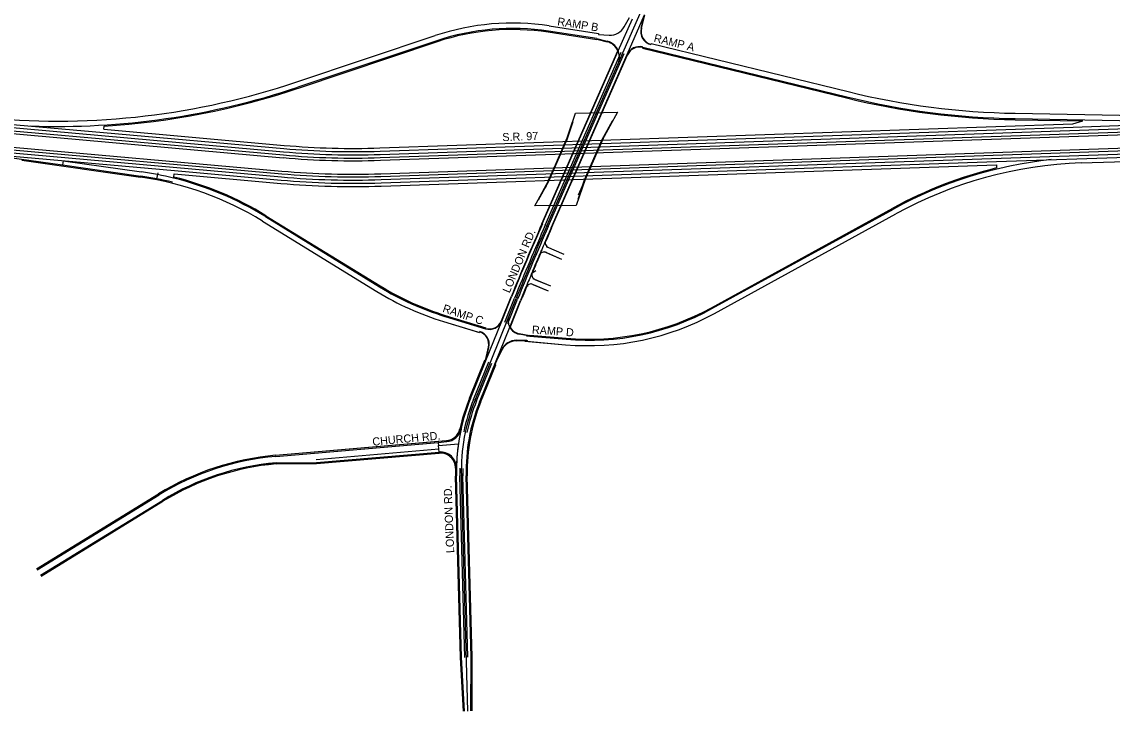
# Model space of a CAD drawing. Extents: x 2315515 to 2326910, y 758186 to 762794.
# Drawn here: x 2318941 to 2323003, y 758186 to 760752 of the extents above; entities that cross this region are included whole.
import ezdxf

# ---------------------------------------------------------------- set-up
doc = ezdxf.new("R2010")
doc.units = 0
for name, color, linetype in [('_CIVIL_CONSTRUCTION', 7, 'Continuous'), ('Bridge_Abutment', 7, 'Continuous'), ('Bridge_Bearing', 7, 'Continuous'), ('Bridge_Deck', 7, 'Continuous'), ('Clipping_Shape', 7, 'Continuous'), ('Default', 7, 'Continuous'), ('Draft_Corr_Final', 7, 'Continuous'), ('Draft_Corr_Range_Final', 7, 'Continuous'), ('Pavement Marking Yellow', 7, 'Continuous'), ('Road_Curb_Face', 7, 'Continuous'), ('TL_Base Extension Sub', 7, 'Continuous'), ('TL_End Condition Cut Tie', 7, 'Continuous'), ('TL_End Condition Ditch Out', 7, 'Continuous'), ('TL_End Condition Hinge', 7, 'Continuous'), ('TL_Pavement Centerline', 7, 'Continuous'), ('TL_Pavement Centerline Sub', 7, 'Continuous')]:
    doc.layers.add(name, color=color, linetype=linetype)

msp = doc.modelspace()

# ---------------------------------------------------------------- linework, layer by layer
at = {"layer": '_CIVIL_CONSTRUCTION'}
for p, q in [((2315523.8, 760636.9), (2319914.5, 760246.1)), ((2315519.4, 760587.1), (2319910, 760196.3)), ((2320276.8, 760236.3), (2324006.3, 760365.3)), ((2320278.5, 760186.3), (2324008.1, 760315.3))]:
    msp.add_line(p, q, dxfattribs=at)
for radius in [2941, 2991]:
    msp.add_arc((2320175.2, 763175.6), radius, 264.9144, 271.9805, dxfattribs=at)
at = {"layer": 'Bridge_Abutment'}
for p, q in [((2320970, 760308.5), (2320994, 760379.5)), ((2321103.2, 760313.3), (2321141.6, 760383.5)), ((2320904.4, 760159.2), (2320970, 760308.5)), ((2321037.2, 760163.2), (2321103.2, 760313.3)), ((2320866, 760089.1), (2320904.4, 760159.2)), ((2321013.2, 760092.1), (2321037.2, 760163.2))]:
    msp.add_line(p, q, dxfattribs=at)
at = {"layer": 'Bridge_Bearing'}
for p, q in [((2320994, 760379.5), (2320970, 760308.5)), ((2321141.6, 760383.5), (2321103.2, 760313.3)), ((2320904.4, 760159.2), (2320970, 760308.5)), ((2321037.2, 760163.2), (2321103.2, 760313.3)), ((2320866, 760089.1), (2320904.4, 760159.2)), ((2321013.2, 760092.1), (2321037.2, 760163.2))]:
    msp.add_line(p, q, dxfattribs=at)
at = {"layer": 'Bridge_Deck'}
for p, q in [((2320891.3, 760134.3), (2320977.7, 760331.1)), ((2320946.3, 760259.5), (2320966.8, 760306.2)), ((2321014.9, 760107.4), (2321107.7, 760318.6)), ((2321083.8, 760264.2), (2321104.3, 760311)), ((2320903.4, 760161.9), (2320924, 760208.7)), ((2321041, 760166.7), (2321061.5, 760213.4))]:
    msp.add_line(p, q, dxfattribs=at)
at = {"layer": 'Clipping_Shape'}
for p, q in [((2320969.1, 760308.8), (2320993.1, 760379.8)), ((2320903.6, 760159.7), (2320969.1, 760308.8)), ((2320865.1, 760089.5), (2320903.6, 760159.7))]:
    msp.add_line(p, q, dxfattribs=at)
msp.add_lwpolyline([(2320852.2, 760066.2), (2320904.3, 760161.4), (2320968.5, 760307.7), (2321003.8, 760411.9), (2321160.3, 760415.2), (2321103.4, 760311.5), (2321039.2, 760165.2), (2321006.2, 760067.6)], close=True, dxfattribs=at)
at = {"layer": 'Default'}
for p, q in [((2320896.6, 759992.2), (2321353.4, 761032.3)), ((2320896.6, 759992.2), (2321353.4, 761032.3)), ((2320896.6, 759992.2), (2321353.4, 761032.3)), ((2320840.7, 759815.8), (2320856, 759826.5)), ((2320820.4, 759766.7), (2320828.3, 759770.7)), ((2320629.4, 759343.1), (2320782.4, 759721.3)), ((2320629.4, 759343.1), (2320782.4, 759721.3)), ((2320629.4, 759343.1), (2320782.4, 759721.3)), ((2320602.3, 758186.1), (2320578.6, 759061.6)), ((2320602.3, 758186.1), (2320578.6, 759061.6)), ((2320602.3, 758186.1), (2320578.6, 759061.6))]:
    msp.add_line(p, q, dxfattribs=at)
for centre, radius, start, end in [((2330052.7, 755971.5), 10000, 156.2923, 157.9768), ((2330052.7, 755971.5), 10000, 156.2923, 157.9768), ((2330052.7, 755971.5), 10000, 156.2923, 157.9768), ((2321278.3, 759080.6), 700, 157.9768, 181.5499), ((2321278.3, 759080.6), 700, 157.9768, 181.5499), ((2321278.3, 759080.6), 700, 157.9768, 181.5499)]:
    msp.add_arc(centre, radius, start, end, dxfattribs=at)
at = {"layer": 'Draft_Corr_Final'}
for p, q in [((2321184.8, 760732.9), (2321204.5, 760767.9)), ((2321248.3, 760728.3), (2321261, 760777.3)), ((2321083.3, 760689.3), (2320902.9, 760716.9)), ((2321083.3, 760689.3), (2321122.2, 760679.3)), ((2321083.3, 760689.3), (2321122.2, 760679.3)), ((2321089.2, 760704.6), (2321129.4, 760702.5)), ((2320487.5, 760681.4), (2319968.8, 760508)), ((2321253.9, 760658.1), (2322014.4, 760472.4)), ((2321253.9, 760658.1), (2322014.4, 760472.4)), ((2320880.1, 759999.4), (2321163, 760643.5)), ((2320880.1, 759999.4), (2321163, 760643.5)), ((2320913.1, 759984.9), (2321196.2, 760629.7)), ((2320913.1, 759984.9), (2321196.2, 760629.7)), ((2322641, 760391.4), (2323391.1, 760378)), ((2322641, 760391.4), (2323391.1, 760378)), ((2319094.8, 760234.8), (2319386.5, 760193.3)), ((2321512.1, 759684), (2322187.7, 760054.5)), ((2321512.1, 759684), (2322187.7, 760054.5)), ((2319848.5, 760026.7), (2320274.1, 759765)), ((2320894.2, 759915.3), (2320960, 759887.1)), ((2320886.3, 759897), (2320952.1, 759868.7)), ((2320895.2, 759893.2), (2320952.1, 759868.7)), ((2320903, 759911.6), (2320960, 759887.1)), ((2320844.8, 759796.2), (2320910.1, 759769.1)), ((2320852.8, 759792.8), (2320910.1, 759769.1)), ((2320837.1, 759777.7), (2320902.4, 759750.7)), ((2320845.2, 759774.4), (2320902.4, 759750.7)), ((2320729.3, 759638), (2320765.7, 759728)), ((2320729.3, 759638), (2320765.7, 759728)), ((2320758.7, 759614.8), (2320799.1, 759714.5)), ((2320758.7, 759614.8), (2320799.1, 759714.5)), ((2320517.6, 759655.1), (2320668.3, 759608.9)), ((2320833, 759581.8), (2320793.5, 759589.3)), ((2320833, 759581.8), (2320793.5, 759589.3)), ((2320782.8, 759566.1), (2320823, 759566.6)), ((2320820.8, 759582.8), (2320968.7, 759569.9)), ((2320833, 759581.8), (2320968.7, 759569.9)), ((2320612.7, 759349.8), (2320680.2, 759516.6)), ((2320669.6, 759490.4), (2320680.9, 759539.8)), ((2320711.7, 759498.5), (2320730.4, 759534)), ((2320612.7, 759349.8), (2320669.6, 759490.4)), ((2320646.1, 759336.3), (2320712.8, 759501.1)), ((2320646.1, 759336.3), (2320711.7, 759498.5)), ((2319886.9, 759134), (2320492.1, 759186.2)), ((2320492.1, 759186.2), (2320523.9, 759189)), ((2320492.1, 759186.2), (2320523.9, 759189)), ((2320492.1, 759186.2), (2320493.2, 759174.3)), ((2320038.8, 759111), (2320495.2, 759150.3)), ((2320038.8, 759111), (2320495.2, 759150.3)), ((2320495.2, 759150.3), (2320493.2, 759174.3)), ((2319889, 759110.1), (2320038.8, 759111)), ((2320578.9, 758385.5), (2320560.6, 759061.2)), ((2320578.9, 758385.5), (2320560.6, 759061.2)), ((2320614.8, 758386.5), (2320596.6, 759062.1)), ((2320614.8, 758386.5), (2320596.6, 759062.1)), ((2318998.3, 758712.1), (2319452.4, 758990.9)), ((2319010.8, 758691.7), (2319464.9, 758970.4)), ((2320590.3, 758185.7), (2320578.9, 758385.5)), ((2320614.3, 758186.4), (2320614.8, 758386.5))]:
    msp.add_line(p, q, dxfattribs=at)
for centre, radius, start, end in [((2320768.6, 759840.1), 887, 81.2923, 108.4803), ((2321132.5, 760762.4), 60, 267.0029, 330.5817), ((2321296.6, 760715.6), 50, 165.3826, 256.2777), ((2321107.3, 760621.2), 60, 336.2923, 75.5817), ((2321107.3, 760621.2), 60, 21.8653, 75.5817), ((2321242, 760609.6), 50, 76.2777, 156.2923), ((2319073, 763188.3), 2826, 268.0003, 288.4803), ((2322691.8, 763246.9), 2856, 256.2777, 268.9805), ((2322691.8, 763246.9), 2856, 256.2777, 268.9805), ((2322940.8, 758681.5), 1566, 96.0766, 118.7415), ((2322940.8, 758681.5), 1566, 96.0766, 118.7415), ((2319216.9, 758999.3), 1206, 76.1189, 81.9144), ((2319216.9, 758999.3), 1206, 58.4184, 76.1189), ((2330052.7, 755971.5), 10018, 156.2923, 157.9768), ((2330052.7, 755971.5), 10018, 156.2923, 157.9768), ((2330052.7, 755971.5), 9982, 156.2923, 156.67031), ((2330052.7, 755971.5), 9982, 156.2923, 156.58701), ((2320910.9, 759929.9), 20, 156.587, 246.7596), ((2330052.7, 755971.5), 9982, 156.82209, 157.38068), ((2330052.7, 755971.5), 9982, 156.93209, 157.32833), ((2320887.3, 759874.8), 20, 66.7596, 156.9321), ((2320860.5, 759811.3), 20, 157.3283, 247.5009), ((2320826.1, 760662.9), 1054, 238.4184, 252.9768), ((2330052.7, 755971.5), 9982, 157.60715, 157.9768), ((2330052.7, 755971.5), 9982, 157.67342, 157.9768), ((2320837.5, 759755.9), 20, 67.5009, 157.6734), ((2321052.4, 760522.2), 956, 264.9768, 298.7415), ((2321052.4, 760522.2), 956, 264.9768, 298.7415), ((2320682.9, 759656.8), 50, 252.9768, 337.9768), ((2320802.8, 759638.4), 50, 157.9768, 259.2662), ((2320632.2, 759551), 50, 347.0671, 72.9768), ((2320802.8, 759638.4), 50, 208.185, 259.2662), ((2320783.5, 759506.1), 60, 90.6874, 152.2662), ((2321278.3, 759080.6), 718, 157.9768, 168.1459), ((2321278.3, 759080.6), 718, 157.9768, 168.1459), ((2321278.3, 759080.6), 682, 157.9768, 181.5499), ((2321278.3, 759080.6), 682, 157.9768, 181.5499), ((2320518.7, 759248.7), 60, 274.9294, 347.5179), ((2320518.7, 759248.7), 60, 274.9294, 347.5179), ((2320500.4, 759090.6), 60, 359.264, 94.9294), ((2321278.3, 759080.6), 718, 172.8394, 181.5499), ((2319972.3, 758143.7), 994, 94.9294, 121.5395), ((2319972.3, 758143.7), 970, 94.9662, 121.5395), ((2321278.3, 759080.6), 718, 179.264, 181.5499)]:
    msp.add_arc(centre, radius, start, end, dxfattribs=at)
msp.add_open_spline([(2319888.4, 759110.1), (2319888.4, 759110.1), (2319888.4, 759110.1), (2319888.4, 759110.1), (2319888.5, 759110.1), (2319888.5, 759110.1), (2319888.5, 759110.1), (2319888.6, 759110.1), (2319888.6, 759110.1), (2319888.6, 759110.1), (2319888.6, 759110.1), (2319888.7, 759110.1), (2319888.7, 759110.1), (2319888.7, 759110.1), (2319888.8, 759110.1), (2319888.8, 759110.1), (2319888.8, 759110.1), (2319888.9, 759110.1), (2319888.9, 759110.1), (2319888.9, 759110.1), (2319889, 759110.1), (2319889, 759110.1), (2319889, 759110.1)], degree=3, dxfattribs=at)
at = {"layer": 'Draft_Corr_Range_Final'}
for p, q in [((2315524.7, 760646.8), (2319915.4, 760256.1)), ((2315518.5, 760577.1), (2319909.2, 760186.4)), ((2320276.5, 760246.3), (2324006, 760375.3)), ((2320278.9, 760176.4), (2324008.4, 760305.3))]:
    msp.add_line(p, q, dxfattribs=at)
for radius in [2931, 3001]:
    msp.add_arc((2320175.2, 763175.6), radius, 264.9144, 271.9805, dxfattribs=at)
at = {"layer": 'Pavement Marking Yellow'}
for p, q in [((2320891.1, 759994.6), (2321174, 760638.7)), ((2320902.1, 759989.8), (2321185, 760633.9)), ((2320740.4, 759633.5), (2320776.8, 759723.5)), ((2320751.5, 759628.9), (2320787.9, 759719)), ((2320623.8, 759345.3), (2320680.7, 759485.9)), ((2320635, 759340.8), (2320691.8, 759481.4)), ((2320590.9, 758385.8), (2320572.6, 759061.5)), ((2320602.9, 758386.2), (2320584.6, 759061.8))]:
    msp.add_line(p, q, dxfattribs=at)
for centre, radius, start, end in [((2330052.7, 755971.5), 10006, 156.2923, 157.9768), ((2330052.7, 755971.5), 9994, 156.2923, 157.9768), ((2321278.3, 759080.6), 706, 157.9768, 168.1459), ((2321278.3, 759080.6), 694, 157.9768, 168.1459), ((2321278.3, 759080.6), 706, 179.264, 181.5499), ((2321278.3, 759080.6), 694, 179.264, 181.5499)]:
    msp.add_arc(centre, radius, start, end, dxfattribs=at)
at = {"layer": 'Road_Curb_Face'}
for p, q in [((2321249.7, 760727.9), (2321262.5, 760776.9)), ((2321249.7, 760727.9), (2321262.5, 760776.8)), ((2321082.9, 760687.8), (2321121.9, 760677.8)), ((2321083.1, 760687.8), (2321121.9, 760677.8)), ((2320878.8, 760000), (2321161.6, 760644.1)), ((2320878.8, 760000), (2321161.4, 760643.5)), ((2320914.5, 759984.3), (2321197.6, 760629.1)), ((2320727.9, 759638.6), (2320764.3, 759728.6)), ((2320727.9, 759638.6), (2320764.3, 759728.6)), ((2320760.1, 759614.2), (2320800.5, 759714)), ((2320760.4, 759614.9), (2320800.5, 759714)), ((2320833.3, 759583.3), (2320793.8, 759590.7)), ((2320833.3, 759583.3), (2320793.8, 759590.7)), ((2320782.8, 759564.6), (2320823, 759565.1)), ((2320668.1, 759490.8), (2320679.5, 759540.1)), ((2320668.2, 759491), (2320679.5, 759540.1)), ((2320713, 759497.8), (2320731.7, 759533.3)), ((2320704.4, 759476.4), (2320713, 759497.8))]:
    msp.add_line(p, q, dxfattribs=at)
for centre, radius, start, end in [((2321296.6, 760715.6), 48.5, 165.3826, 256.2777), ((2321296.6, 760715.6), 48.5, 165.3826, 256.2777), ((2321107.3, 760621.2), 58.5, 23.8009, 75.5817), ((2321107.3, 760621.2), 58.5, 22.4792, 75.5817), ((2321242, 760609.6), 48.5, 76.2777, 156.2923), ((2330052.7, 755971.5), 10019.5, 156.2923, 157.9768), ((2330052.7, 755971.5), 10019.5, 156.2923, 157.9768), ((2330052.7, 755971.5), 9980.5, 156.2923, 156.58701), ((2330052.7, 755971.5), 9980.5, 156.93209, 157.33984), ((2330052.7, 755971.5), 9980.5, 157.66192, 157.9768), ((2330052.7, 755971.5), 9980.5, 157.66192, 157.9768), ((2320682.9, 759656.8), 48.5, 252.9768, 337.9768), ((2320632.2, 759551), 48.5, 347.0671, 72.9768), ((2320632.2, 759551), 48.5, 347.0671, 72.9768), ((2320802.8, 759638.4), 48.5, 209.0103, 259.2662), ((2320802.8, 759638.4), 48.5, 212.6887, 259.2662), ((2320783.5, 759506.1), 58.5, 90.6874, 152.2662)]:
    msp.add_arc(centre, radius, start, end, dxfattribs=at)
at = {"layer": 'TL_Base Extension Sub'}
for p, q in [((2315525.8, 760658.8), (2319916.4, 760268.1)), ((2315517.4, 760565.2), (2319908.1, 760174.4)), ((2320276.1, 760258.3), (2324005.6, 760387.3)), ((2320279.3, 760164.4), (2324008.8, 760293.3)), ((2320037.8, 759122.9), (2320494.2, 759162.3))]:
    msp.add_line(p, q, dxfattribs=at)
for radius in [2919, 3013]:
    msp.add_arc((2320175.2, 763175.6), radius, 264.9144, 271.9805, dxfattribs=at)
at = {"layer": 'TL_End Condition Cut Tie'}
for p, q in [((2320905.9, 760736.7), (2321089.8, 760708.5)), ((2319962.4, 760527), (2320481.1, 760700.4)), ((2321082.7, 760685.3), (2320902.3, 760713)), ((2321089.8, 760708.5), (2321089.2, 760704.6)), ((2320488.7, 760677.6), (2319970, 760504.2)), ((2321253.9, 760658.1), (2321252.9, 760654.3)), ((2321252.9, 760654.3), (2322013.4, 760468.6)), ((2321284.8, 760667.1), (2321285.7, 760671)), ((2321285.7, 760671), (2322019.1, 760491.9)), ((2322641.4, 760411.4), (2323583.4, 760394.6)), ((2319246.6, 760351.8), (2319247.7, 760363.7)), ((2322641, 760387.4), (2322893.8, 760382.9)), ((2322856.6, 760371.6), (2322893.8, 760382.9)), ((2322887.3, 760226.5), (2323387, 760243.8)), ((2322887.3, 760226.5), (2323387, 760243.8)), ((2318941.1, 760236.4), (2319383.7, 760173.5)), ((2318941.1, 760236.4), (2319383.7, 760173.5)), ((2322572, 760219.6), (2322572.4, 760207.6)), ((2319507.2, 760174), (2319508.3, 760185.9)), ((2321510.1, 759687.5), (2322185.8, 760058)), ((2321521.7, 759666.4), (2322197.4, 760037)), ((2321521.7, 759666.4), (2322197.4, 760037)), ((2319838, 760009.6), (2320263.7, 759748)), ((2319838, 760009.6), (2320263.7, 759748)), ((2319850.6, 760030.1), (2320276.2, 759768.4)), ((2320511.7, 759636), (2320638.4, 759597.2)), ((2320511.7, 759636), (2320645.7, 759595)), ((2320518.7, 759658.9), (2320669.5, 759612.8)), ((2320646.8, 759598.8), (2320645.7, 759595)), ((2320815.4, 759563.2), (2320966.9, 759549.9)), ((2320823.2, 759566.6), (2320822.8, 759562.6)), ((2320822.8, 759562.6), (2320966.9, 759549.9)), ((2320833.4, 759581.7), (2320833.7, 759585.7)), ((2320833.7, 759585.7), (2320969, 759573.8)), ((2320609, 759351.3), (2320665.9, 759491.9)), ((2320649.8, 759334.8), (2320706.7, 759475.4)), ((2320669.6, 759490.4), (2320665.9, 759491.9)), ((2320703, 759476.9), (2320706.7, 759475.4)), ((2319886.6, 759138), (2320523.5, 759192.9)), ((2319886.6, 759138), (2320507.4, 759191.5)), ((2320039, 759107), (2320495.6, 759146.4)), ((2320039.2, 759107), (2320495.6, 759146.4)), ((2319888.5, 759106.1), (2320039, 759107)), ((2319889, 759106.1), (2320038.9, 759107)), ((2320574.9, 758385.4), (2320556.6, 759061)), ((2320574.9, 758385.3), (2320556.6, 759061)), ((2320618.8, 758386.6), (2320600.6, 759062.2)), ((2318996.2, 758715.5), (2319450.3, 758994.3)), ((2318996.2, 758715.5), (2319450.3, 758994.3)), ((2319012.9, 758688.3), (2319467, 758967)), ((2319012.9, 758688.3), (2319467, 758967)), ((2320586.3, 758185.5), (2320574.9, 758385.3)), ((2320586.3, 758185.5), (2320574.9, 758385.3)), ((2320618.3, 758186.4), (2320618.8, 758386.5)), ((2320618.3, 758186.4), (2320618.8, 758386.5))]:
    msp.add_line(p, q, dxfattribs=at)
for centre, radius, start, end in [((2320768.6, 759840.1), 907, 81.2923, 108.4803), ((2320768.6, 759840.1), 883, 81.2923, 108.4803), ((2319073, 763188.3), 2806, 264.9144, 288.4803), ((2319073, 763188.3), 2830, 273.5389, 288.4803), ((2322691.8, 763246.9), 2836, 256.2777, 268.9805), ((2322691.8, 763246.9), 2860, 256.2777, 268.9805), ((2322940.8, 758681.5), 1570, 103.5684, 118.7415), ((2322940.8, 758681.5), 1546, 91.9805, 118.7415), ((2322940.8, 758681.5), 1546, 91.9805, 118.7415), ((2319216.9, 758999.3), 1186, 58.4184, 81.9144), ((2319216.9, 758999.3), 1186, 58.4184, 81.9144), ((2319216.9, 758999.3), 1210, 58.4184, 76.1189), ((2320826.1, 760662.9), 1050, 238.4184, 252.9768), ((2320826.1, 760662.9), 1074, 238.4184, 252.9768), ((2320826.1, 760662.9), 1074, 238.4184, 252.9768), ((2321052.4, 760522.2), 952, 264.9768, 298.7415), ((2321052.4, 760522.2), 976, 264.9768, 298.7415), ((2321052.4, 760522.2), 976, 264.9768, 298.7415), ((2321278.3, 759080.6), 722, 157.9768, 167.5179), ((2321278.3, 759080.6), 678, 157.9768, 181.5499), ((2320518.7, 759248.7), 56, 274.9294, 347.5179), ((2320518.7, 759248.7), 56, 274.9294, 347.5179), ((2320500.4, 759090.6), 56, 359.264, 94.9294), ((2319972.3, 758143.7), 998, 94.9294, 121.5395), ((2319972.3, 758143.7), 998, 94.9294, 121.5395), ((2319972.3, 758143.7), 966, 94.9662, 121.5395), ((2319972.3, 758143.7), 966, 94.9761, 121.5395), ((2321278.3, 759080.6), 722, 179.264, 181.5499), ((2321278.3, 759080.6), 722, 179.264, 181.5499)]:
    msp.add_arc(centre, radius, start, end, dxfattribs=at)
at = {"layer": 'TL_End Condition Ditch Out'}
for p, q in [((2321196.2, 760629.7), (2321261, 760777.3)), ((2321163, 760643.5), (2321215.5, 760763.1)), ((2318013.8, 760449.4), (2319245.5, 760339.8)), ((2322857, 760359.6), (2323696.6, 760388.6)), ((2318790.3, 760261.9), (2319509.3, 760197.9)), ((2322571.6, 760231.6), (2323686.3, 760270.2)), ((2320669.6, 759490.4), (2320729.3, 759638)), ((2320703, 759476.9), (2320758.7, 759614.8))]:
    msp.add_line(p, q, dxfattribs=at)
for centre, radius, start, end in [((2330052.7, 755971.5), 9982, 156.58701, 156.93209), ((2330052.7, 755971.5), 9982, 157.33984, 157.66192), ((2321278.3, 759080.6), 718, 167.5179, 179.264)]:
    msp.add_arc(centre, radius, start, end, dxfattribs=at)
at = {"layer": 'TL_End Condition Hinge'}
for p, q in [((2318790.3, 760261.9), (2319092.5, 760218.9)), ((2319094.8, 760234.8), (2319092.5, 760218.9)), ((2319092.5, 760218.9), (2319384.3, 760177.5)), ((2319444.7, 760167.3), (2319449, 760190)), ((2320493.2, 759174.3), (2320567.3, 759180.7))]:
    msp.add_line(p, q, dxfattribs=at)
msp.add_arc((2319216.9, 758999.3), 1190, 76.1189, 81.9144, dxfattribs=at)
at = {"layer": 'TL_Pavement Centerline'}
for p, q in [((2319245.5, 760339.8), (2319917.5, 760280)), ((2320275.6, 760270.3), (2322857, 760359.6)), ((2320279.7, 760152.4), (2322571.6, 760231.6)), ((2319509.3, 760197.9), (2319907, 760162.5))]:
    msp.add_line(p, q, dxfattribs=at)
for radius in [2907, 3025]:
    msp.add_arc((2320175.2, 763175.6), radius, 264.9144, 271.9805, dxfattribs=at)
at = {"layer": 'TL_Pavement Centerline Sub'}
for p, q in [((2320275.2, 760282.3), (2322856.6, 760371.6)), ((2319246.6, 760351.8), (2319918.6, 760292)), ((2320280.1, 760140.4), (2322572, 760219.6)), ((2319508.3, 760185.9), (2319906, 760150.5))]:
    msp.add_line(p, q, dxfattribs=at)
for radius in [2895, 3037]:
    msp.add_arc((2320175.2, 763175.6), radius, 264.9144, 271.9805, dxfattribs=at)

# ---------------------------------------------------------------- texts
at = {"layer": 'Default'}
for s, rotation, p in [('RAMP B', 351.3639, (2320934.5, 760739)), ('RAMP A', 346.2856, (2321293.4, 760678.2)), ('S.R. 97', 2.1074, (2320731.7, 760307.5)), ('LONDON RD.', 67.0887, (2320757.9, 759740)), ('RAMP C', 341.6007, (2320506.3, 759672.7)), ('RAMP D', 355.8776, (2320840.6, 759591.4)), ('CHURCH RD.', 5.3529, (2320248.5, 759173.5)), ('LONDON RD.', 92.2882, (2320552.1, 758774.7))]:
    msp.add_text(s, height=30, rotation=rotation, dxfattribs=at).set_placement(p)

doc.saveas('drawing.dxf')
